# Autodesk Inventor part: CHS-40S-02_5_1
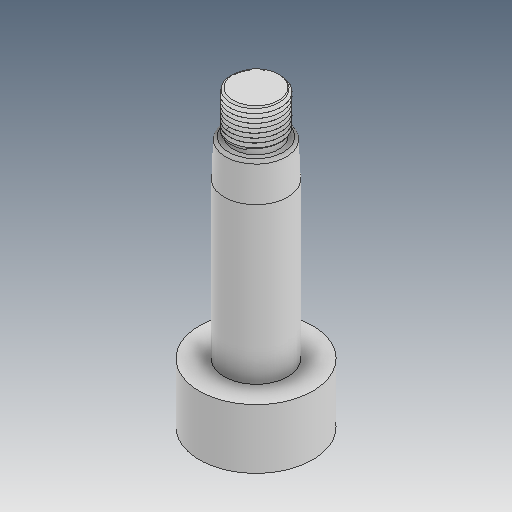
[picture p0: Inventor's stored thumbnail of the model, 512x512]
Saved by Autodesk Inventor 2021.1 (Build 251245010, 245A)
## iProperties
Created: 2019-04
Part Number: CHS-40S-02_5_1
Material: Ogólny
Document SubType Name: Modeling
Designer: user
Density: 1 g/cm^3
Appearance: Domyślna
Author: user
Revision Number: ÈÎºÎ
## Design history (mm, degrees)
feature "ÊäÈë1"
feature "ÊäÈë2"
node "Bryła1"
node "Bryła2"
